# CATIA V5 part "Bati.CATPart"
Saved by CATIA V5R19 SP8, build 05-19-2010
Part number: Bati
Bounding box of the stored display mesh (mm): x -40 to 40, y -70 to 538, z 577 to 759.996
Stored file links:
  G:\EU_thinkMotion\CFAO_2010\MMS_groupe3\MMS_groupe3\A reprendre\fovide\fovide\Bati.CATPart
  G:\EU_thinkMotion\CFAO_2010\MMS_groupe3\MMS_groupe3\A reprendre\fovide\fovide\fovide.CATProduct
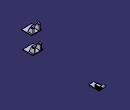
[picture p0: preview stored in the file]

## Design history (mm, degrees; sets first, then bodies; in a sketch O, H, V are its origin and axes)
Set1
  Plane1: linked copy from another document
  Line1: linked copy from another document
  Plane2: linked copy from another document
  Point1 "Point.A": linked copy from another document
  Plane3: linked copy from another document
  Point2 "Point.O": linked copy from another document
  Plane4: linked copy from another document
  Line2: linked copy from another document
  Plane5: linked copy from another document
  Point3 "Point.I": linked copy from another document
  Line3: linked copy from another document
Body1 (main body)
  Sketch1 on Plane2, origin (0, 0, 0), H (0, 1, 0), V (0, 0, 1)
    arc A1 centre (0, 750) radius 10 from (-9.0384, 754.2788) to (10, 750) cw
    point P1 (0, 750)
    reference projected point E1 (0, 750) from Point1
    line L1 (10, 750) -> (10, 710)
    point P4 (10, 710)
    line L2 (10, 710) -> (-30, 710)
    point P5 (-30, 710)
    line L3 (-30, 710) -> (-9.0384, 754.2788)
    reference projected point E2 (10, 710) from vertex [element of Sketch2 | element of Sketch2]
    reference projected point E3 (-30, 710) from vertex [element of Sketch2 | element of Sketch2]
    radius A1 = 10
    coincidence: P1 E1, P4 E2, P5 E3
    horizontal: L2 H
    tangency: L3 A1, L1 A1
  Sketch2 on Plane1, origin (0, 0, 710), H (1, 0, 0), V (0, 1, 0)
    line L1 (20, 10) -> (30, 10)
    line L2 (30, 10) -> (30, -30)
    line L3 (30, -30) -> (20, -30)
    line L4 (20, -30) -> (20, 10)
    reference projected line E1 (-50, 0) -> (50, 0) from Line1
    reference intersected line E2 through (0, 0) direction (0, 1) from Plane2
    length L2 = 40
    distance L1 E1 = 10
    length L1 = 10
    distance L4 E2 = 20
    horizontal: L1 H, L3 H
    vertical: L2 V, L4 V
  SolidCombine1: FirstComponentProfile Sketch1, FirstComponentDirection Sketch1, SecondComponentProfile Sketch2, SecondComponentDirection Sketch2
  Sketch3 on Plane1, origin (0, 0, 710), H (1, 0, 0), V (0, 1, 0)
    line L1 (-30, 10) -> (-20, 10)
    line L2 (-20, 10) -> (-20, -30)
    line L3 (-20, -30) -> (-30, -30)
    line L4 (-30, -30) -> (-30, 10)
    reference projected line E1 (-50, 0) -> (50, 0) from Line1
    reference intersected line E2 through (0, 0) direction (0, 1) from Plane2
    distance L1 E1 = 10
    length L1 = 10
    distance L2 E2 = 20
    length L2 = 40
    horizontal: L1 H, L3 H
    vertical: L2 V, L4 V
  SolidCombine2: FirstComponentProfile Sketch3, FirstComponentDirection Sketch3, SecondComponentProfile Sketch1, SecondComponentDirection Sketch1
  Sketch4 on face of SolidCombine1 from Sketch2.L2, origin (30, 0, 750), H (0, 1, 0), V (0, 0, 1)
    point P1 (0, 0)
    intersected point E1 (0, 0) from Line1
    coincidence: E1 P1
  Hole1: placed by Sketch4, at (30, 0, 750) direction (-1, 0, 0), diameter 10, through (limit type 3)
  Sketch5 on Plane2, origin (0, 0, 0), H (0, 1, 0), V (0, 0, 1)
    line L1 (10, 710) -> (-70, 710)
    line L2 (-70, 710) -> (-70, 707)
    line L3 (-70, 707) -> (10, 707)
    line L4 (10, 707) -> (10, 710)
    reference intersected line E1 through (0, 710) direction (-1, 0) from Plane1
    reference projected line E2 (10, 710) -> (10, 750) from edge [face of SolidCombine1 from Sketch2.L1 | face of SolidCombine1 from Sketch2.L2]
    length L4 = 3
    length L3 = 80
    horizontal: L1 H, L3 H
    vertical: L2 V, L4 V
    coincidence: L1 E1, L4 E2
  Pad1: profile Sketch5, direction (1, 0, 0), length 40, mirrored extent
  Sketch6 on Plane3, origin (0, 0, 0), H (0, 1, 0), V (0, 0, 1)
    arc A1 centre (10, 620) radius 10 from (0.9616, 624.2788) to (20, 620) cw
    point P1 (10, 620)
    reference projected point E1 (10, 620) from Point2
    line L1 (20, 620) -> (20, 580)
    line L2 (20, 580) -> (-20, 580)
    line L3 (-20, 580) -> (0.9616, 624.2788)
    reference intersected line E2 through (0, 580) direction (-1, 0) from Plane4
    radius A1 = 10
    length L2 = 40
    coincidence: P1 E1, L2 E2
    horizontal: L2 H
    tangency: L3 A1, L1 A1
    vertical: L1 V
  Sketch7 on Plane4, origin (0, 0, 580), H (1, 0, 0), V (0, 1, 0)
    line L1 (20, 20) -> (30, 20)
    line L2 (30, 20) -> (30, -20)
    line L3 (30, -20) -> (20, -20)
    line L4 (20, -20) -> (20, 20)
    reference projected line E1 (-50, 10) -> (50, 10) from Line2
    reference intersected line E2 through (0, 0) direction (0, 1) from Plane3
    distance L1 E1 = 10
    length L2 = 40
    length L1 = 10
    distance L4 E2 = 20
    horizontal: L1 H, L3 H
    vertical: L2 V, L4 V
  SolidCombine3: FirstComponentProfile Sketch6, FirstComponentDirection Sketch6, SecondComponentProfile Sketch7, SecondComponentDirection Sketch7
  Sketch8 on Plane4, origin (0, 0, 580), H (1, 0, 0), V (0, 1, 0)
    line L1 (-30, 20) -> (-20, 20)
    line L2 (-20, 20) -> (-20, -20)
    line L3 (-20, -20) -> (-30, -20)
    line L4 (-30, -20) -> (-30, 20)
    reference intersected line E1 through (0, 0) direction (0, 1) from Plane3
    reference projected line E2 (-50, 10) -> (50, 10) from Line2
    length L1 = 10
    distance L2 E1 = 20
    length L4 = 40
    distance L1 E2 = 10
    horizontal: L1 H, L3 H
    vertical: L2 V, L4 V
  SolidCombine4: FirstComponentProfile Sketch8, FirstComponentDirection Sketch8, SecondComponentProfile Sketch6, SecondComponentDirection Sketch6
  Sketch9 on Plane3, origin (0, 0, 0), H (0, 1, 0), V (0, 0, 1)
    line L1 (-60, 580) -> (20, 580)
    line L2 (20, 580) -> (20, 577)
    line L3 (20, 577) -> (-60, 577)
    line L4 (-60, 577) -> (-60, 580)
    reference intersected line E1 through (0, 580) direction (-1, 0) from Plane4
    reference projected line E2 (20, 580) -> (20, 620) from edge [face of SolidCombine3 from Sketch7.L1 | face of SolidCombine3 from Sketch7.L2]
    length L2 = 3
    length L3 = 80
    horizontal: L1 H, L3 H
    vertical: L2 V, L4 V
    coincidence: L1 E1, L2 E2
  Pad2: profile Sketch9, direction (1, 0, 0), length 40, mirrored extent
  Sketch10 on Plane5, origin (0, 0, 0), H (0, 1, 0), V (0, 0, 1)
    arc A1 centre (530, 600) radius 8 from (523.9009, 605.1769) to (535.4597, 594.1526) cw
    point P1 (530, 600)
    reference projected point E1 (530, 600) from Point3
    line L1 (523.9009, 605.1769) -> (514.8413, 594.5034)
    line L2 (514.8413, 594.5034) -> (480.8413, 594.5034)
    line L3 (480.8413, 594.5034) -> (480.8413, 580.5034)
    line L4 (480.8413, 580.5034) -> (520.8413, 580.5034)
    line L5 (520.8413, 580.5034) -> (535.4597, 594.1526)
    radius A1 = 8
    length L4 = 40
    length L5 = 20
    length L3 = 14
    length L1 = 14
    length L2 = 34
    coincidence: P1 E1
    tangency: L1 A1, L5 A1
    horizontal: L2 H, L4 H
    vertical: L3 V
  Pad3: profile Sketch10, direction (1, 0, 0), length 13, mirrored extent
  Sketch11 on end face of Pad3, origin (13, 0, 0), H (0, 1, 0), V (0, 0, 1)
    line L1 (482.8413, 592.5034) -> (515.021, 592.5034)
    line L2 (515.021, 592.5034) -> (520.4369, 597.9321)
    line L3 (520.4369, 597.9321) -> (528.2681, 590.1193)
    line L4 (528.2681, 590.1193) -> (520.6701, 582.5034)
    line L5 (520.6701, 582.5034) -> (482.8413, 582.5034)
    line L6 (482.8413, 582.5034) -> (482.8413, 592.5034)
    reference projected line E1 (514.8413, 594.5034) -> (480.8413, 594.5034) from edge [face of Pad3 from Sketch10.L2 | end face of Pad3]
    reference projected line E2 (480.8413, 580.5034) -> (520.8413, 580.5034) from edge [face of Pad3 from Sketch10.L4 | end face of Pad3]
    reference projected line E3 (480.8413, 594.5034) -> (480.8413, 580.5034) from edge [face of Pad3 from Sketch10.L3 | end face of Pad3]
    distance L1 E1 = 2
    distance L5 E2 = 2
    distance L6 E3 = 2
    horizontal: L1 H, L5 H
    perpendicularity: L3 L2
    parallelism: L4 L2
    vertical: L6 V
  Pocket1: profile Sketch11, direction (-1, 0, 0), length 5
  Sketch12 on start face of Pad3, origin (-13, 0, 0), H (0, -1, 0), V (0, 0, 1)
    line L1 (-482.8413, 592.5034) -> (-482.8413, 582.5034)
    line L2 (-482.8413, 582.5034) -> (-520.7311, 582.5034)
    line L3 (-520.7311, 582.5034) -> (-528.4033, 589.6669)
    line L4 (-528.4033, 589.6669) -> (-519.9729, 598.2667)
    line L5 (-519.9729, 598.2667) -> (-515.081, 592.5034)
    line L6 (-515.081, 592.5034) -> (-482.8413, 592.5034)
    reference projected line E1 (-514.8413, 594.5034) -> (-480.8413, 594.5034) from edge [start face of Pad3 | face of Pad3 from Sketch10.L2]
    reference projected line E2 (-480.8413, 594.5034) -> (-480.8413, 580.5034) from edge [start face of Pad3 | face of Pad3 from Sketch10.L3]
    reference projected line E3 (-480.8413, 580.5034) -> (-520.8413, 580.5034) from edge [start face of Pad3 | face of Pad3 from Sketch10.L4]
    reference projected line E4 (-523.9009, 605.1769) -> (-514.8413, 594.5034) from edge [start face of Pad3 | face of Pad3 from Sketch10.L1]
    reference projected line E5 (-520.8413, 580.5034) -> (-535.4597, 594.1526) from edge [start face of Pad3 | face of Pad3 from Sketch10.L5]
    distance L6 E1 = 2
    distance L1 E2 = 2
    distance L2 E3 = 2
    vertical: L1 V
    horizontal: L2 H, L6 H
    parallelism: L5 E4, L3 E5
  Pocket2: profile Sketch12, direction (1, 0, 0), length 5
  Fillet1: radius 0.5, on end face of Pad3; start face of Pad3
  Sketch13 on Plane5, origin (0, 0, 0), H (0, 1, 0), V (0, 0, 1)
    line L1 (440.8413, 580.5034) -> (520.8413, 580.5034)
    line L2 (520.8413, 580.5034) -> (520.8413, 577.5034)
    line L3 (520.8413, 577.5034) -> (440.8413, 577.5034)
    line L4 (440.8413, 577.5034) -> (440.8413, 580.5034)
    reference projected line E1 (480.8413, 580.5034) -> (520.8413, 580.5034) from edge [face of Pad3 from Sketch10.L4 | face of Fillet1]
    reference projected line E2 (480.8413, 594.5034) -> (480.8413, 580.5034) from edge [face of Pad3 from Sketch10.L3 | face of Fillet1]
    distance L2 E2 = 40
    length L3 = 80
    length L2 = 3
    horizontal: L1 H, L3 H
    vertical: L2 V, L4 V
    coincidence: L1 E1
  Pad4: profile Sketch13, direction (1, 0, 0), length 20, mirrored extent
  Sketch14 on end face of Pad3, origin (13, 530, 600), H (0, 1, 0), V (0, 0, 1)
    point P1 (0, 0)
    intersected point E1 (0, 0) from Line3
    coincidence: E1 P1
  Hole2: placed by Sketch14, at (13, 530, 600) direction (-1, 0, 0), diameter 10, through (limit type 3)
  Sketch15 on face of SolidCombine3 from Sketch7.L2, origin (30, 10, 620), H (0, 1, 0), V (0, 0, 1)
    point P1 (0, 0)
    intersected point E1 (0, 0) from Line2
    coincidence: E1 P1
  Hole3: placed by Sketch15, at (30, 10, 620) direction (-1, 0, 0), diameter 10, through (limit type 3)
